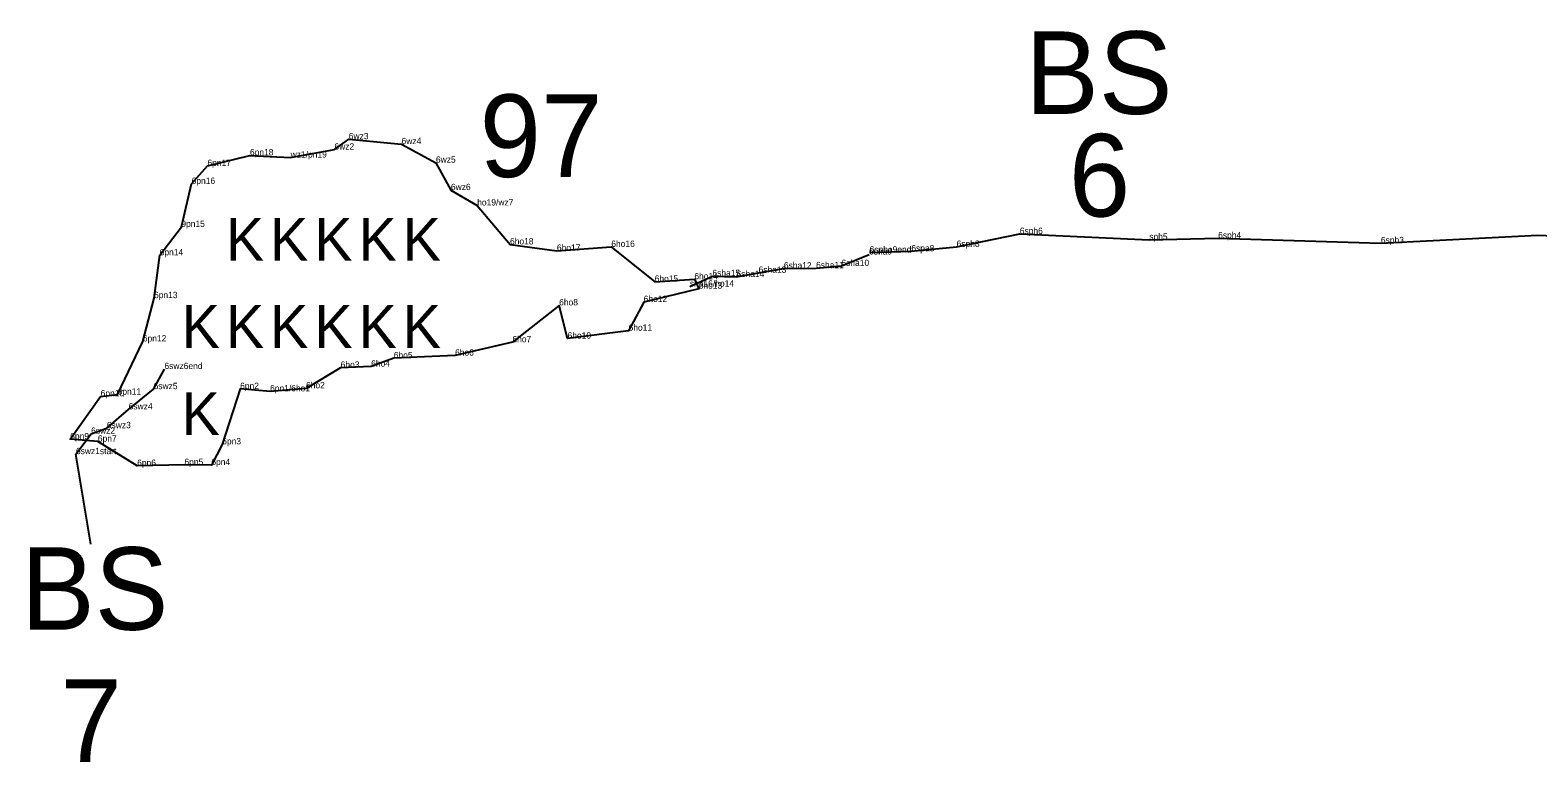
# Model space of a CAD drawing. Extents: x 2072529 to 2268812, y 436423 to 470008.
# Drawn here: x 2136565 to 2137758, y 443227 to 443807 of the extents above; entities that cross this region are included whole.
import ezdxf

# ---------------------------------------------------------------- set-up
doc = ezdxf.new("R2010")
doc.units = 0
for name, color, linetype in [('Old_Level_10', 7, 'Continuous'), ('Old_Level_20', 7, 'Continuous'), ('Old_Level_52', 7, 'Continuous'), ('Old_Level_55', 7, 'Continuous'), ('Old_Level_60', 7, 'Continuous'), ('Old_Level_62', 7, 'Continuous')]:
    doc.layers.add(name, color=color, linetype=linetype)

msp = doc.modelspace()

# ---------------------------------------------------------------- linework, layer by layer
at = {"layer": 'Old_Level_10'}
for points in [[(2137229.441, 443630.485), (2137262.467, 443631.481), (2137298.296, 443635.023), (2137348.313, 443645.249), (2137450.812, 443640.684), (2137505.349, 443641.801), (2137634.157, 443637.885), (2137758.275, 443644.36), (2137809.978, 443642.053)], [(2137087.177, 443603.578), (2137105.046, 443611.893), (2137124.128, 443611.181), (2137141.558, 443614.475), (2137161.593, 443617.915), (2137187.056, 443618.15), (2137207.131, 443619.896), (2137228.98, 443628.949)], [(2136601.21, 443470.92), (2136613.225, 443487.06), (2136625.658, 443491.457), (2136642.932, 443506.338), (2136662.68, 443522.379), (2136671.274, 443538.278)], [(2136601.21, 443470.92), (2136613.225, 443487.06), (2136625.658, 443491.457), (2136642.932, 443506.338), (2136662.68, 443522.379), (2136671.274, 443538.278)]]:
    msp.add_lwpolyline(points, dxfattribs=at)
at = {"layer": 'Old_Level_20'}
for p, q in [((2136805.826, 443712.041), (2136805.826, 443712.041)), ((2136817.181, 443720.196), (2136817.181, 443720.196)), ((2136858.952, 443716.337), (2136858.952, 443716.337)), ((2136705.324, 443699.091), (2136705.324, 443699.091)), ((2136738.942, 443707.427), (2136738.942, 443707.427)), ((2136771.144, 443705.717), (2136771.144, 443705.717)), ((2136886.158, 443701.664), (2136886.158, 443701.664)), ((2136692.793, 443684.884), (2136692.793, 443684.884)), ((2136898.024, 443679.944), (2136898.024, 443679.944)), ((2136918.851, 443667.768), (2136918.851, 443667.768)), ((2136684.637, 443650.81), (2136684.637, 443650.81)), ((2136944.802, 443636.955), (2136944.802, 443636.955)), ((2137348.313, 443645.249), (2137348.313, 443645.249)), ((2137450.812, 443640.684), (2137450.812, 443640.684)), ((2137505.349, 443641.801), (2137505.349, 443641.801)), ((2137634.157, 443637.885), (2137634.157, 443637.885)), ((2137758.275, 443644.36), (2137758.275, 443644.36)), ((2136667.484, 443628.358), (2136667.484, 443628.358)), ((2136981.935, 443631.929), (2136981.935, 443631.929)), ((2137024.987, 443634.997), (2137024.987, 443634.997)), ((2137228.98, 443628.949), (2137228.98, 443628.949)), ((2137229.441, 443630.485), (2137229.441, 443630.485)), ((2137262.467, 443631.481), (2137262.467, 443631.481)), ((2137298.296, 443635.023), (2137298.296, 443635.023)), ((2137141.558, 443614.475), (2137141.558, 443614.475)), ((2137161.593, 443617.915), (2137161.593, 443617.915)), ((2137187.056, 443618.15), (2137187.056, 443618.15)), ((2137207.131, 443619.896), (2137207.131, 443619.896)), ((2137059.319, 443607.416), (2137059.319, 443607.416)), ((2137087.177, 443603.578), (2137087.177, 443603.578)), ((2137090.731, 443609.337), (2137090.731, 443609.337)), ((2137094.182, 443601.915), (2137094.182, 443601.915)), ((2137105.046, 443611.893), (2137105.046, 443611.893)), ((2137124.128, 443611.181), (2137124.128, 443611.181)), ((2136663.01, 443594.418), (2136663.01, 443594.418)), ((2137050.598, 443591.352), (2137050.598, 443591.352)), ((2136983.703, 443588.66), (2136983.703, 443588.66)), ((2137038.662, 443568.652), (2137038.662, 443568.652)), ((2136654.149, 443560.114), (2136654.149, 443560.114)), ((2136946.739, 443559.494), (2136946.739, 443559.494)), ((2136990.374, 443562.383), (2136990.374, 443562.383)), ((2136852.792, 443546.807), (2136852.792, 443546.807)), ((2136901.3, 443548.937), (2136901.3, 443548.937)), ((2136671.274, 443538.278), (2136671.274, 443538.278)), ((2136671.274, 443538.278), (2136671.274, 443538.278)), ((2136810.744, 443539.309), (2136810.744, 443539.309)), ((2136834.88, 443540.228), (2136834.88, 443540.228)), ((2136634.205, 443518.021), (2136634.205, 443518.021)), ((2136662.68, 443522.379), (2136662.68, 443522.379)), ((2136662.68, 443522.379), (2136662.68, 443522.379)), ((2136731.175, 443522.503), (2136731.175, 443522.503)), ((2136754.889, 443520.601), (2136754.889, 443520.601)), ((2136783.332, 443523.009), (2136783.332, 443523.009)), ((2136620.759, 443516.657), (2136620.759, 443516.657)), ((2136642.932, 443506.338), (2136642.932, 443506.338)), ((2136642.932, 443506.338), (2136642.932, 443506.338)), ((2136596.676, 443482.667), (2136596.676, 443482.667)), ((2136613.225, 443487.06), (2136613.225, 443487.06)), ((2136613.225, 443487.06), (2136613.225, 443487.06)), ((2136625.658, 443491.457), (2136625.658, 443491.457)), ((2136625.658, 443491.457), (2136625.658, 443491.457)), ((2136601.21, 443470.92), (2136601.21, 443470.92)), ((2136601.21, 443470.92), (2136601.21, 443470.92)), ((2136618.572, 443480.848), (2136618.572, 443480.848)), ((2136717.008, 443478.66), (2136717.008, 443478.66)), ((2136649.679, 443461.63), (2136649.679, 443461.63)), ((2136687.097, 443462.332), (2136687.097, 443462.332)), ((2136708.386, 443462.3), (2136708.386, 443462.3))]:
    msp.add_line(p, q, dxfattribs=at)
at = {"layer": 'Old_Level_52'}
msp.add_lwpolyline([(2136771.144, 443705.717), (2136805.826, 443712.041), (2136817.181, 443720.196), (2136858.952, 443716.337), (2136886.158, 443701.664), (2136898.024, 443679.944), (2136918.851, 443667.768), (2136944.802, 443636.955), (2136981.935, 443631.929), (2137024.987, 443634.997), (2137059.319, 443607.416), (2137090.731, 443609.337), (2137094.182, 443601.915), (2137050.598, 443591.352), (2137038.662, 443568.652), (2136990.374, 443562.383), (2136983.703, 443588.66), (2136946.739, 443559.494), (2136901.3, 443548.937), (2136852.792, 443546.807), (2136834.88, 443540.228), (2136810.744, 443539.309), (2136783.332, 443523.009), (2136754.889, 443520.601), (2136731.175, 443522.503), (2136717.008, 443478.66), (2136708.386, 443462.3), (2136687.097, 443462.332), (2136649.679, 443461.63), (2136618.572, 443480.848), (2136596.676, 443482.667), (2136620.759, 443516.657), (2136634.205, 443518.021), (2136654.149, 443560.114), (2136663.01, 443594.418), (2136667.484, 443628.358), (2136684.637, 443650.81), (2136692.793, 443684.884), (2136705.324, 443699.091), (2136738.942, 443707.427)], close=True, dxfattribs=at)
at = {"layer": 'Old_Level_62'}
msp.add_line((2136612.954, 443399.696), (2136601.21, 443470.92), dxfattribs=at)

# ---------------------------------------------------------------- texts
at = {"layer": 'Old_Level_55'}
for p in [(2136719.862, 443623.964), (2136754.862, 443623.964), (2136789.862, 443623.964), (2136824.862, 443623.964), (2136859.862, 443623.964), (2136684.862, 443554.964), (2136719.862, 443554.964), (2136754.862, 443554.964), (2136789.862, 443554.964), (2136824.862, 443554.964), (2136859.862, 443554.964), (2136684.862, 443485.964)]:
    msp.add_text('K', height=34, dxfattribs=at).set_placement(p)
at = {"layer": 'Old_Level_60'}
for s, p in [('6wz3', (2136817.181, 443720.196)), ('6wz4', (2136858.952, 443716.337)), ('6pn18', (2136738.942, 443707.427)), ('wz1/pn19', (2136771.144, 443705.717)), ('6wz2', (2136805.826, 443712.041)), ('6pn17', (2136705.324, 443699.091)), ('6wz5', (2136886.158, 443701.664)), ('6pn16', (2136692.793, 443684.884)), ('6wz6', (2136898.024, 443679.944)), ('ho19/wz7', (2136918.851, 443667.768)), ('9pn15', (2136684.637, 443650.81)), ('6sph6', (2137348.313, 443645.249)), ('6ho18', (2136944.802, 443636.955)), ('6ho17', (2136981.935, 443631.929)), ('6ho16', (2137024.987, 443634.997)), ('6sph8', (2137298.296, 443635.023)), ('sph5', (2137450.812, 443640.684)), ('6sph4', (2137505.349, 443641.801)), ('6sph3', (2137634.157, 443637.885)), ('6pn14', (2136667.484, 443628.358)), ('6sha10', (2137207.131, 443619.896)), ('6sha9', (2137228.98, 443628.949)), ('6spha9end', (2137229.441, 443630.485)), ('6spa8', (2137262.467, 443631.481)), ('6ho14', (2137090.731, 443609.337)), ('6sha15', (2137105.046, 443611.893)), ('6sha14', (2137124.128, 443611.181)), ('6sha13', (2137141.558, 443614.475)), ('6sha12', (2137161.593, 443617.915)), ('6sha11', (2137187.056, 443618.15)), ('6ho15', (2137059.319, 443607.416)), ('sha16/ho14', (2137087.177, 443603.578)), ('6ho13', (2137094.182, 443601.915)), ('6pn13', (2136663.01, 443594.418)), ('6ho8', (2136983.703, 443588.66)), ('6ho12', (2137050.598, 443591.352)), ('6ho10', (2136990.374, 443562.383)), ('6ho11', (2137038.662, 443568.652)), ('6pn12', (2136654.149, 443560.114)), ('6ho6', (2136901.3, 443548.937)), ('6ho7', (2136946.739, 443559.494)), ('6swz6end', (2136671.274, 443538.278)), ('6swz6end', (2136671.274, 443538.278)), ('6ho3', (2136810.744, 443539.309)), ('6ho4', (2136834.88, 443540.228)), ('6ho5', (2136852.792, 443546.807)), ('6pn10', (2136620.759, 443516.657)), ('6pn11', (2136634.205, 443518.021)), ('6swz5', (2136662.68, 443522.379)), ('6swz5', (2136662.68, 443522.379)), ('6pn2', (2136731.175, 443522.503)), ('6pn1/6ho1', (2136754.889, 443520.601)), ('6ho2', (2136783.332, 443523.009)), ('6swz4', (2136642.932, 443506.338)), ('6swz4', (2136642.932, 443506.338)), ('6swz3', (2136625.658, 443491.457)), ('6swz3', (2136625.658, 443491.457)), ('6pn9', (2136596.676, 443482.667)), ('6swz2', (2136613.225, 443487.06)), ('6swz2', (2136613.225, 443487.06)), ('6pn7', (2136618.572, 443480.848)), ('6pn3', (2136717.008, 443478.66)), ('6swz1start', (2136601.21, 443470.92)), ('6swz1start', (2136601.21, 443470.92)), ('6pn6', (2136649.679, 443461.63)), ('6pn5', (2136687.097, 443462.332)), ('6pn4', (2136708.386, 443462.3))]:
    msp.add_text(s, height=5, dxfattribs=at).set_placement(p)
at = {"layer": 'Old_Level_62'}
for s, p in [('BS', (2137352.631, 443740.264)), ('97', (2136920.741, 443690.313)), ('6', (2137387.136, 443659.051)), ('BS', (2136557.791, 443331.867)), ('7', (2136588.954, 443227.323))]:
    msp.add_text(s, height=65.34, dxfattribs=at).set_placement(p)

doc.saveas('drawing.dxf')
